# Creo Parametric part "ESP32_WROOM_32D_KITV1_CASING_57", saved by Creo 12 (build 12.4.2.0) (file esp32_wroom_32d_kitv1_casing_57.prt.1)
Units: Custom; MM, KILOGRAM, SECS

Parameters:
  PTC_WM_ITERATION = "0"
  PTC_WM_VERSION = "-.0"
  PTC_WM_LIFECYCLE_STATE = "In Work"
  PTC_WM_LIFECYCLE = "MO_CADDocument"
  PTC_WM_CREATED_BY = "Maximilian Roepper (Z0017RMS: MO)"
  PTC_WM_CREATED_ON = "18-Sep-26 11:36:42 AM"
  PTC_WM_MODIFIED_BY = "Maximilian Roepper (Z0017RMS: MO)"
  PTC_WM_MODIFIED_ON = "18-Sep-26 11:36:46 AM"
  PDMLINKNUMBER = "PDM000071454790"
  PTC_WM_NAME = "esp32_wroom_32d_kitv1_casing_57.prt"
  PTC_WM_NUMBER = "PDM000071454790"

Other parameters: WEIGHT, WEIGHT_FACTOR, WEIGHT_ADD, _MASS_TEMP, _DIFF_TEMP, MC_ERRORS, SUPPLIER

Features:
  1. coordinate system
  2. datum plane "PRT_YZ"
  3. datum plane "PRT_XY"
  4. datum plane "PRT_XZ"
  5. coordinate system
  6. datum axis
  7. datum axis
  8. datum axis
  9. coordinate system
  10. imported feature
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
Other named items: PRT, SIEMENS_MO, DRW_VIEW_ORG, PRT_X, PRT_Y, PRT_Z, CS0, ROUGH_GROB

Layers: 00_STD_CSYS-KSYS, 01_STD_PLANES-EBENEN, 02_STD_AXES-ACHSEN, 03_STD_CSYS-KSYS, 24_IMPORT_FEAT-IMPORT_KE

Surfaces: 5 plane, 1 cylinder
